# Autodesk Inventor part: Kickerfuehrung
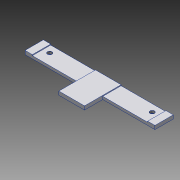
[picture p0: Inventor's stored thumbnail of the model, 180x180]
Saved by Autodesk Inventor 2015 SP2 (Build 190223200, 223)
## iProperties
Created: 2015-08
Part Number: Kickerfuehrung
Material: Aluminium 6061
Document SubType Name: Modeling
Designer: rYan
Mass: 3.78 g
Surface Area: 8.8 cm^2
Volume: 1.4 cm^3
Density: 2.7 g/cm^3
Appearance: Aluminium - flach
Author: rYan
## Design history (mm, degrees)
sketch "Skizze3"
  geometry: L1 (35.5, 0)-(35.5, -10); L2 (-35.5, -10)-(-35.5, 0); L3 (-7, 0)-(7, 0); L4 (7, -20)-(-7, -20); L5 (-35.5, 0)-(-7, 0); L6 (7, 0)-(35.5, 0); L7 (-7, -20)-(-7, -10); L8 (-7, 0)-(-7, 0); L9 (7, 0)-(7, 0); L10 (7, -10)-(7, -20); L11 (35.5, -10)-(7, -10); L12 (-7, -10)-(-35.5, -10); L13 (0, 4)-(0, -24) reference; L14 (-49.7, 0)-(49.7, 0) reference; 1 further point
  constraints: 24 end point, 10 parallel, 4 perpendicular, 3 collinear, 3 horizontal, 5 other
  dimensions: "d21" = 10 distance of L2.start L2.end; "d22" = 71 distance between parallel lines of L1 L2; "d24" = 14 distance of L3.start L3.end; "d25" = 10 distance of L10.start L4.start
extrude "Extrusion2" new body sketch "Skizze3" distance "d26" = 1.5; taper "d27" = 0 deg
sketch "Skizze5"
  geometry: L1 (35.5, 0)-(-35.5, 0) reference; L2 (7, -20)-(-7, -20); L3 (-7, -20)-(-7, 0); L4 (-7, 0)-(7, 0); L5 (7, 0)-(7, -20); L6 (-7, -10)-(-7, -20) reference
  constraints: 8 end point, 2 parallel, 1 collinear, 1 horizontal, 1 perpendicular, 1 point on line
extrude "Extrusion3" join sketch "Skizze5" distance "d38" = 0.5; taper "d39" = 0 deg
sketch "Skizze6"
  geometry: L1 (35.5, 0)-(31.5, 0); L2 (31.5, 0)-(31.5, -10); L3 (31.5, -10)-(35.5, -10); L4 (35.5, -10)-(35.5, 0); L5 (7, -10)-(35.5, -10) reference; 1 further point
  constraints: 8 end point, 2 parallel, 1 collinear, 1 horizontal, 1 perpendicular
  dimensions: "d40" = 4 distance of L1.start L1.end
extrude "Extrusion4" join sketch "Skizze6" distance "d41" = 0.5; taper "d42" = 0 deg
sketch "Skizze4"
  geometry: L1 (-35.5, 0)-(-35.5, -10) reference; L2 (-35.5, -10)-(-7, -10) reference; L3 (7, -10)-(31.5, -10) reference; L4 (-28, -4)-(28, -4); L5 (0, 4)-(0, -24) reference; L6 (7, 0)-(7, -10) reference; L7 (-7, -10)-(-7, 0) reference; L8 (-7, 0)-(-35.5, 0) reference; L9 (31.5, -10)-(31.5, 0) reference; L10 (31.5, 0)-(7, 0) reference; 3 further points
  constraints: 2 coincident, 2 end point, 1 horizontal, 1 symmetric about line
  dimensions: "d30" = 56 distance of L4.start L4.end; "d43" = 4 distance between parallel lines of L8 L4
hole "Bohrung2" sketch "Skizze4" at (-28, -4), (28, -4) diameter "d31" = 2.459; stored, may be unused: countersink angle "d35" = 90 deg, drill point angle "d37" = 118 deg; dims "d32" = 6, "d33" = 4, "d34" = 2, "d36" = 8.8
mirror "Spiegeln1"
node "Volumenkörper2"
node "Projizierte Kontur2"
